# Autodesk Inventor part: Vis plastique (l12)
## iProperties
Author: Flavien MARTY
Shininess: 60.0
PropertySet Name: _Private Model Information
Created: 2001-10
Part Number: Vis plastique (l12)
Material: Par défaut
Document SubType Name: Modélisation
Designer: Flavien MARTY
Control State: 0
Master: False
Checked Out: False
PropertySet Name: Design Tracking Control
Density: 0.0
Volumn: 0.0
Area: 0.0
PropertySet Name: Model Information
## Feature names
1. Base1
